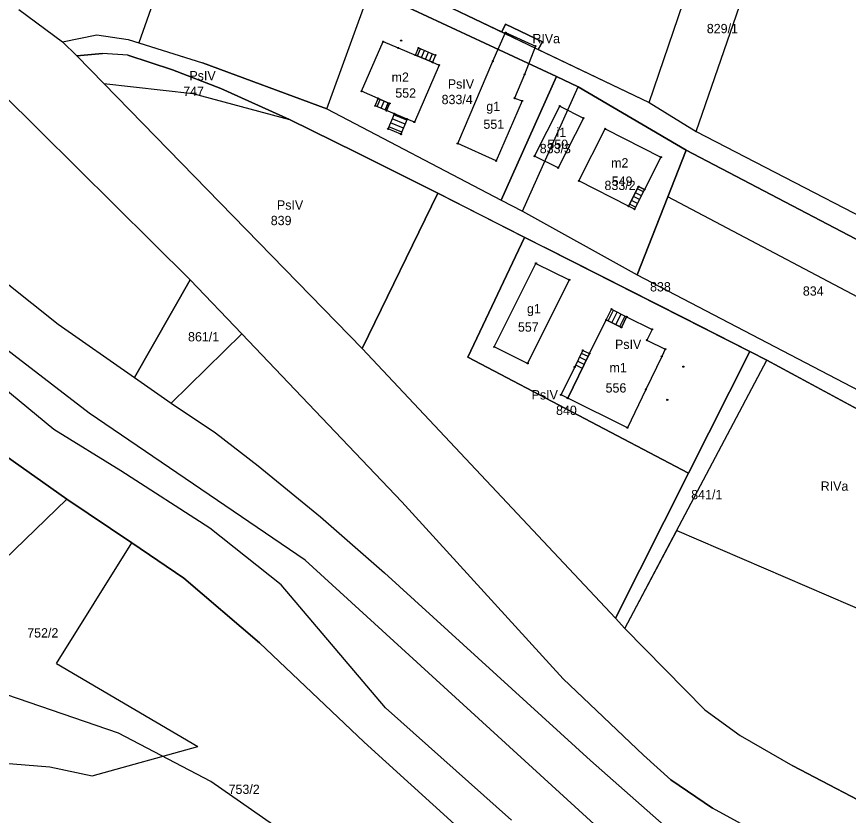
# Model space of a CAD drawing. Extents: x 7498273 to 7499989, y 5499795 to 5500810.
# Drawn here: x 7499073.7 to 7499207.8, y 5500392.1 to 5500521 of the extents above; entities that cross this region are included whole.
import ezdxf

# ---------------------------------------------------------------- set-up
doc = ezdxf.new("R2010")
doc.units = 0
for name, color, linetype in [('209-oznaczenie konturu klasyfikacyjnego', 7, 'Continuous'), ('211-numer działki ewidencyjnej', 7, 'Continuous'), ('217-kontur klasyfikacyjny', 7, 'Continuous'), ('218-kontur użytku gruntowego', 7, 'Continuous'), ('219-działka ewidencyjna', 7, 'Continuous'), ('312-budynek ewidencyjny', 7, 'Continuous'), ('312-oznaczenie budynku ewidencyjnego', 7, 'Continuous'), ('312-oznaczenie budynku ewidencyjnego-Atr117', 7, 'Continuous'), ('352-schody', 7, 'Continuous'), ('Punkt budynku', 7, 'Continuous')]:
    doc.layers.add(name, color=color, linetype=linetype)

# ---------------------------------------------------------------- blocks, each defined once
blk = doc.blocks.new('PUNKTBUD')
blk.add_circle((0, 0), 0.09)

msp = doc.modelspace()

# ---------------------------------------------------------------- linework, layer by layer
at = {"layer": '217-kontur klasyfikacyjny'}
for points in [[(7499101.11, 5500538.76), (7499093.36, 5500516.77)], [(7499131.62, 5500528.27), (7499151.94, 5500518.51)], [(7499123.69, 5500506.08), (7499130.71, 5500525.33)], [(7499160.73, 5500511.31), (7499130.71, 5500525.33)], [(7499151.94, 5500518.51), (7499152.51, 5500519.76)], [(7499152.51, 5500519.76), (7499158.46, 5500516.91)], [(7499151.94, 5500518.51), (7499157.81, 5500515.69)], [(7499093.36, 5500516.77), (7499103.62, 5500513.55)], [(7499158.46, 5500516.91), (7499157.81, 5500515.69)], [(7499087.53, 5500515.03), (7499083.37, 5500514.64)], [(7499083.37, 5500514.64), (7499087.71, 5500510.21)], [(7499091.59, 5500514.76), (7499087.53, 5500515.03)], [(7499098.81, 5500512.41), (7499091.59, 5500514.76)], [(7499157.81, 5500515.69), (7499175.67, 5500507.11)], [(7499103.62, 5500513.55), (7499123.69, 5500506.08)], [(7499106.58, 5500509.41), (7499098.81, 5500512.41)], [(7499151.82, 5500491.39), (7499160.73, 5500511.31)], [(7499160.73, 5500511.31), (7499164.26, 5500509.66)], [(7499087.71, 5500510.21), (7499102.1, 5500508.58)], [(7499087.71, 5500510.21), (7499129.4, 5500467.46)], [(7499117.68, 5500504.37), (7499106.58, 5500509.41)], [(7499164.26, 5500509.66), (7499181.67, 5500499.42)], [(7499101.66, 5500478.53), (7499071.27, 5500508.65)], [(7499102.1, 5500508.58), (7499117.68, 5500504.37)], [(7499175.67, 5500507.11), (7499183.28, 5500502.46)], [(7499123.69, 5500506.08), (7499151.82, 5500491.39)], [(7499128.46, 5500499.07), (7499117.68, 5500504.37)], [(7499183.28, 5500502.46), (7499226.11, 5500480.31)], [(7499141.59, 5500492.5), (7499128.46, 5500499.07)], [(7499181.67, 5500499.42), (7499178.7, 5500491.9)], [(7499227.23, 5500475.57), (7499181.67, 5500499.42)], [(7499129.4, 5500467.46), (7499141.59, 5500492.5)], [(7499155.6, 5500485.37), (7499141.59, 5500492.5)], [(7499178.7, 5500491.9), (7499173.73, 5500479.35)], [(7499296.61, 5500429.63), (7499178.7, 5500491.9)], [(7499055.34, 5500491.27), (7499080.34, 5500471.35)], [(7499146.42, 5500466.04), (7499155.6, 5500485.37)], [(7499158.26, 5500484.02), (7499155.6, 5500485.37)], [(7499159.07, 5500483.61), (7499158.26, 5500484.02)], [(7499181.06, 5500472.48), (7499159.07, 5500483.61)], [(7499092.66, 5500462.75), (7499101.66, 5500478.53)], [(7499109.96, 5500469.81), (7499101.66, 5500478.53)], [(7499173.73, 5500479.35), (7499219.39, 5500455.52)], [(7499191.93, 5500466.97), (7499181.06, 5500472.48)], [(7499080.34, 5500471.35), (7499092.66, 5500462.75)], [(7499135.77, 5500442.73), (7499109.96, 5500469.81)], [(7499129.4, 5500467.46), (7499170.26, 5500423.96)], [(7499182.05, 5500447.36), (7499191.93, 5500466.97)], [(7499194.67, 5500465.58), (7499191.93, 5500466.97)], [(7499182.05, 5500447.36), (7499146.42, 5500466.04)], [(7499234.45, 5500444.08), (7499194.67, 5500465.58)], [(7499092.66, 5500462.75), (7499098.6, 5500458.65)], [(7499098.6, 5500458.65), (7499105.72, 5500453.82)], [(7499105.72, 5500453.82), (7499112.62, 5500448.53)], [(7499081.74, 5500443.12), (7499071.81, 5500450.17)], [(7499112.62, 5500448.53), (7499122.67, 5500440.29)], [(7499170.26, 5500423.96), (7499182.05, 5500447.36)], [(7499092.26, 5500436.09), (7499081.74, 5500443.12)], [(7499161.8, 5500414.19), (7499135.77, 5500442.73)], [(7499122.67, 5500440.29), (7499132.99, 5500431.26)], [(7499171.77, 5500422.29), (7499180.14, 5500438.11)], [(7499180.14, 5500438.11), (7499222.1, 5500420.02)], [(7499100.61, 5500430.41), (7499092.26, 5500436.09)], [(7499112.82, 5500419.97), (7499100.61, 5500430.41)], [(7499132.99, 5500431.26), (7499166.22, 5500400.98)], [(7499170.26, 5500423.96), (7499171.77, 5500422.29)], [(7499171.77, 5500422.29), (7499184.68, 5500409.19)], [(7499129.71, 5500403.95), (7499112.82, 5500419.97)], [(7499090.07, 5500405.4), (7499064.84, 5500414.07)], [(7499174.8, 5500401.83), (7499161.8, 5500414.19)], [(7499184.68, 5500409.19), (7499190.39, 5500405)], [(7499104.96, 5500397.6), (7499090.07, 5500405.4)], [(7499190.39, 5500405), (7499198.84, 5500400.12)], [(7499155.37, 5500380.67), (7499129.71, 5500403.95)], [(7499166.22, 5500400.98), (7499189.5, 5500380.47)], [(7499179.19, 5500397.85), (7499174.8, 5500401.83)], [(7499198.84, 5500400.12), (7499214.07, 5500392.18)], [(7499128.22, 5500381.42), (7499104.96, 5500397.6)], [(7499185.89, 5500393.28), (7499179.19, 5500397.85)], [(7499197.4, 5500387.02), (7499185.89, 5500393.28)]]:
    msp.add_lwpolyline(points, dxfattribs=at)
at = {"layer": '218-kontur użytku gruntowego'}
for points in [[(7499101.11, 5500538.76), (7499093.36, 5500516.77)], [(7499131.62, 5500528.27), (7499151.94, 5500518.51)], [(7499123.69, 5500506.08), (7499130.71, 5500525.33)], [(7499160.73, 5500511.31), (7499130.71, 5500525.33)], [(7499073.99, 5500522.1), (7499081.08, 5500516.92)], [(7499152.51, 5500519.76), (7499151.94, 5500518.51)], [(7499158.46, 5500516.91), (7499152.51, 5500519.76)], [(7499081.08, 5500516.92), (7499086.58, 5500518.05)], [(7499086.58, 5500518.05), (7499091.64, 5500517.31)], [(7499091.64, 5500517.31), (7499093.36, 5500516.77)], [(7499151.94, 5500518.51), (7499157.81, 5500515.69)], [(7499093.36, 5500516.77), (7499103.62, 5500513.55)], [(7499157.81, 5500515.69), (7499158.46, 5500516.91)], [(7499087.53, 5500515.03), (7499083.37, 5500514.64)], [(7499083.37, 5500514.64), (7499087.71, 5500510.21)], [(7499091.59, 5500514.76), (7499087.53, 5500515.03)], [(7499098.81, 5500512.41), (7499091.59, 5500514.76)], [(7499157.81, 5500515.69), (7499175.67, 5500507.11)], [(7499103.62, 5500513.55), (7499123.69, 5500506.08)], [(7499106.58, 5500509.41), (7499098.81, 5500512.41)], [(7499160.73, 5500511.31), (7499151.82, 5500491.39)], [(7499164.26, 5500509.66), (7499160.73, 5500511.31)], [(7499087.71, 5500510.21), (7499102.1, 5500508.58)], [(7499087.71, 5500510.21), (7499129.4, 5500467.46)], [(7499117.68, 5500504.37), (7499106.58, 5500509.41)], [(7499181.67, 5500499.42), (7499164.26, 5500509.66)], [(7499101.66, 5500478.53), (7499071.27, 5500508.65)], [(7499102.1, 5500508.58), (7499117.68, 5500504.37)], [(7499175.67, 5500507.11), (7499183.28, 5500502.46)], [(7499123.69, 5500506.08), (7499151.82, 5500491.39)], [(7499128.46, 5500499.07), (7499117.68, 5500504.37)], [(7499183.28, 5500502.46), (7499226.11, 5500480.31)], [(7499141.59, 5500492.5), (7499128.46, 5500499.07)], [(7499181.67, 5500499.42), (7499178.7, 5500491.9)], [(7499227.23, 5500475.57), (7499181.67, 5500499.42)], [(7499085.38, 5500457), (7499035.99, 5500494.95)], [(7499141.59, 5500492.5), (7499129.4, 5500467.46)], [(7499155.6, 5500485.37), (7499141.59, 5500492.5)], [(7499178.7, 5500491.9), (7499173.73, 5500479.35)], [(7499296.61, 5500429.63), (7499178.7, 5500491.9)], [(7499055.34, 5500491.27), (7499080.34, 5500471.35)], [(7499151.82, 5500491.39), (7499155.28, 5500489.58)], [(7499155.28, 5500489.58), (7499173.73, 5500479.35)], [(7499155.6, 5500485.37), (7499146.42, 5500466.04)], [(7499158.26, 5500484.02), (7499155.6, 5500485.37)], [(7499159.07, 5500483.61), (7499158.26, 5500484.02)], [(7499181.06, 5500472.48), (7499159.07, 5500483.61)], [(7499079.66, 5500454.39), (7499047.93, 5500480.59)], [(7499101.66, 5500478.53), (7499092.66, 5500462.75)], [(7499109.96, 5500469.81), (7499101.66, 5500478.53)], [(7499173.73, 5500479.35), (7499219.39, 5500455.52)], [(7499191.93, 5500466.97), (7499181.06, 5500472.48)], [(7499080.34, 5500471.35), (7499092.66, 5500462.75)], [(7499135.77, 5500442.73), (7499109.96, 5500469.81)], [(7499129.4, 5500467.46), (7499170.26, 5500423.96)], [(7499191.93, 5500466.97), (7499182.05, 5500447.36)], [(7499194.67, 5500465.58), (7499191.93, 5500466.97)], [(7499146.42, 5500466.04), (7499182.05, 5500447.36)], [(7499234.45, 5500444.08), (7499194.67, 5500465.58)], [(7499092.66, 5500462.75), (7499098.6, 5500458.65)], [(7499098.6, 5500458.65), (7499105.72, 5500453.82)], [(7499120.19, 5500433.29), (7499085.38, 5500457)], [(7499090.49, 5500447.7), (7499079.66, 5500454.39)], [(7499105.72, 5500453.82), (7499112.62, 5500448.53)], [(7499071.81, 5500450.17), (7499081.74, 5500443.12)], [(7499104.8, 5500438.49), (7499090.49, 5500447.7)], [(7499112.62, 5500448.53), (7499122.67, 5500440.29)], [(7499182.05, 5500447.36), (7499170.26, 5500423.96)], [(7499081.74, 5500443.12), (7499092.26, 5500436.09)], [(7499161.8, 5500414.19), (7499135.77, 5500442.73)], [(7499122.67, 5500440.29), (7499132.99, 5500431.26)], [(7499116.34, 5500429.34), (7499104.8, 5500438.49)], [(7499171.77, 5500422.29), (7499180.14, 5500438.11)], [(7499180.14, 5500438.11), (7499222.1, 5500420.02)], [(7499092.26, 5500436.09), (7499100.61, 5500430.41)], [(7499171.15, 5500386.77), (7499120.19, 5500433.29)], [(7499100.61, 5500430.41), (7499112.82, 5500419.97)], [(7499132.99, 5500431.26), (7499166.22, 5500400.98)], [(7499133.15, 5500409.51), (7499116.34, 5500429.34)], [(7499170.26, 5500423.96), (7499171.77, 5500422.29)], [(7499171.77, 5500422.29), (7499184.68, 5500409.19)], [(7499112.82, 5500419.97), (7499129.71, 5500403.95)], [(7499090.07, 5500405.4), (7499064.84, 5500414.07)], [(7499174.8, 5500401.83), (7499161.8, 5500414.19)], [(7499153.5, 5500391.37), (7499133.15, 5500409.51)], [(7499184.68, 5500409.19), (7499190.39, 5500405)], [(7499104.96, 5500397.6), (7499090.07, 5500405.4)], [(7499190.39, 5500405), (7499198.84, 5500400.12)], [(7499129.71, 5500403.95), (7499155.37, 5500380.67)], [(7499166.22, 5500400.98), (7499189.5, 5500380.47)], [(7499179.19, 5500397.85), (7499174.8, 5500401.83)], [(7499198.84, 5500400.12), (7499214.07, 5500392.18)], [(7499128.22, 5500381.42), (7499104.96, 5500397.6)], [(7499185.89, 5500393.28), (7499179.19, 5500397.85)], [(7499197.4, 5500387.02), (7499185.89, 5500393.28)]]:
    msp.add_lwpolyline(points, dxfattribs=at)
at = {"layer": '219-działka ewidencyjna'}
for points in [[(7499175.67, 5500507.11), (7499185.88, 5500537.14)], [(7499183.28, 5500502.46), (7499194.31, 5500534.37)], [(7499131.62, 5500528.27), (7499175.67, 5500507.11)], [(7499123.69, 5500506.08), (7499130.71, 5500525.33)], [(7499130.71, 5500525.33), (7499160.73, 5500511.31)], [(7499073.99, 5500522.1), (7499081.08, 5500516.92)], [(7499081.08, 5500516.92), (7499086.58, 5500518.05)], [(7499086.58, 5500518.05), (7499091.64, 5500517.31)], [(7499091.64, 5500517.31), (7499103.62, 5500513.55)], [(7499081.08, 5500516.92), (7499083.37, 5500514.64)], [(7499083.37, 5500514.64), (7499087.53, 5500515.03)], [(7499083.37, 5500514.64), (7499087.71, 5500510.21)], [(7499091.59, 5500514.76), (7499087.53, 5500515.03)], [(7499091.59, 5500514.76), (7499098.81, 5500512.41)], [(7499123.69, 5500506.08), (7499103.62, 5500513.55)], [(7499098.81, 5500512.41), (7499106.58, 5500509.41)], [(7499151.82, 5500491.39), (7499160.73, 5500511.31)], [(7499160.73, 5500511.31), (7499164.26, 5500509.66)], [(7499087.71, 5500510.21), (7499129.4, 5500467.46)], [(7499087.71, 5500510.21), (7499102.1, 5500508.58)], [(7499106.58, 5500509.41), (7499117.68, 5500504.37)], [(7499155.28, 5500489.58), (7499164.26, 5500509.66)], [(7499164.26, 5500509.66), (7499181.67, 5500499.42)], [(7499071.27, 5500508.65), (7499101.66, 5500478.53)], [(7499102.1, 5500508.58), (7499117.68, 5500504.37)], [(7499175.67, 5500507.11), (7499183.28, 5500502.46)], [(7499123.69, 5500506.08), (7499151.82, 5500491.39)], [(7499117.68, 5500504.37), (7499128.46, 5500499.07)], [(7499183.28, 5500502.46), (7499226.11, 5500480.31)], [(7499128.46, 5500499.07), (7499141.59, 5500492.5)], [(7499173.73, 5500479.35), (7499181.67, 5500499.42)], [(7499181.67, 5500499.42), (7499227.23, 5500475.57)], [(7499129.4, 5500467.46), (7499141.59, 5500492.5)], [(7499141.59, 5500492.5), (7499159.07, 5500483.61)], [(7499055.34, 5500491.27), (7499080.34, 5500471.35)], [(7499151.82, 5500491.39), (7499155.28, 5500489.58)], [(7499155.28, 5500489.58), (7499173.73, 5500479.35)], [(7499159.07, 5500483.61), (7499191.93, 5500466.97)], [(7499092.66, 5500462.75), (7499101.66, 5500478.53)], [(7499101.66, 5500478.53), (7499109.96, 5500469.81)], [(7499173.73, 5500479.35), (7499219.39, 5500455.52)], [(7499080.34, 5500471.35), (7499092.66, 5500462.75)], [(7499098.6, 5500458.65), (7499109.96, 5500469.81)], [(7499109.96, 5500469.81), (7499135.77, 5500442.73)], [(7499129.4, 5500467.46), (7499170.26, 5500423.96)], [(7499170.26, 5500423.96), (7499191.93, 5500466.97)], [(7499191.93, 5500466.97), (7499194.67, 5500465.58)], [(7499171.77, 5500422.29), (7499194.67, 5500465.58)], [(7499194.67, 5500465.58), (7499266.92, 5500426.53)], [(7499092.66, 5500462.75), (7499098.6, 5500458.65)], [(7499098.6, 5500458.65), (7499105.72, 5500453.82)], [(7499105.72, 5500453.82), (7499112.62, 5500448.53)], [(7499071.81, 5500450.17), (7499081.74, 5500443.12)], [(7499112.62, 5500448.53), (7499122.67, 5500440.29)], [(7499058.06, 5500420.25), (7499081.74, 5500443.12)], [(7499081.74, 5500443.12), (7499092.26, 5500436.09)], [(7499135.77, 5500442.73), (7499161.8, 5500414.19)], [(7499122.67, 5500440.29), (7499132.99, 5500431.26)], [(7499080.08, 5500416.64), (7499092.26, 5500436.09)], [(7499092.26, 5500436.09), (7499100.61, 5500430.41)], [(7499100.61, 5500430.41), (7499112.82, 5500419.97)], [(7499166.22, 5500400.98), (7499132.99, 5500431.26)], [(7499170.26, 5500423.96), (7499171.77, 5500422.29)], [(7499171.77, 5500422.29), (7499184.68, 5500409.19)], [(7499112.82, 5500419.97), (7499129.71, 5500403.95)], [(7499080.08, 5500416.64), (7499102.88, 5500403.24)], [(7499161.8, 5500414.19), (7499174.8, 5500401.83)], [(7499184.68, 5500409.19), (7499190.39, 5500405)], [(7499190.39, 5500405), (7499198.84, 5500400.12)], [(7499129.71, 5500403.95), (7499155.37, 5500380.67)], [(7499085.87, 5500398.54), (7499102.88, 5500403.24)], [(7499064.37, 5500401.18), (7499079.03, 5500399.99)], [(7499166.22, 5500400.98), (7499189.5, 5500380.47)], [(7499174.8, 5500401.83), (7499179.19, 5500397.85)], [(7499079.03, 5500399.99), (7499085.87, 5500398.54)], [(7499214.07, 5500392.18), (7499198.84, 5500400.12)], [(7499179.19, 5500397.85), (7499185.89, 5500393.28)], [(7499197.4, 5500387.02), (7499185.89, 5500393.28)]]:
    msp.add_lwpolyline(points, dxfattribs=at)
at = {"layer": '312-budynek ewidencyjny'}
for points in [[(7499150.46, 5500513.8), (7499152.54, 5500518.39)], [(7499152.54, 5500518.39), (7499157.35, 5500516.21)], [(7499129.3, 5500508.94), (7499132.77, 5500516.95)], [(7499132.77, 5500516.95), (7499135.2, 5500515.93)], [(7499157.35, 5500516.21), (7499155.57, 5500511.63)], [(7499135.2, 5500515.93), (7499137.98, 5500514.77)], [(7499137.98, 5500514.77), (7499140.75, 5500513.61)], [(7499140.75, 5500513.61), (7499141.82, 5500513.16)], [(7499144.8, 5500500.51), (7499150.46, 5500513.8)], [(7499141.82, 5500513.16), (7499137.81, 5500503.97)], [(7499155.57, 5500511.63), (7499153.96, 5500507.83)], [(7499131.99, 5500507.77), (7499129.3, 5500508.94)], [(7499133.83, 5500506.98), (7499131.99, 5500507.77)], [(7499133.33, 5500505.81), (7499133.83, 5500506.98)], [(7499155.21, 5500507.37), (7499151.01, 5500497.71)], [(7499153.96, 5500507.83), (7499155.21, 5500507.37)], [(7499157.21, 5500498.47), (7499161.29, 5500506.56)], [(7499161.29, 5500506.56), (7499165.11, 5500504.6)], [(7499134.59, 5500505.29), (7499133.33, 5500505.81)], [(7499136.65, 5500504.45), (7499134.59, 5500505.29)], [(7499137.81, 5500503.97), (7499136.65, 5500504.45)], [(7499165.11, 5500504.6), (7499161, 5500496.58)], [(7499164.35, 5500494.48), (7499168.6, 5500502.88)], [(7499168.6, 5500502.88), (7499177.59, 5500498.3)], [(7499151.01, 5500497.71), (7499144.8, 5500500.51)], [(7499161, 5500496.58), (7499157.21, 5500498.47)], [(7499177.59, 5500498.3), (7499174.93, 5500493.07)], [(7499172.37, 5500490.39), (7499164.35, 5500494.48)], [(7499173.98, 5500493.56), (7499172.37, 5500490.39)], [(7499174.93, 5500493.07), (7499173.98, 5500493.56)], [(7499150.69, 5500467.7), (7499157.43, 5500481.18)], [(7499157.43, 5500481.18), (7499162.81, 5500478.52)], [(7499162.81, 5500478.52), (7499156.09, 5500465.05)], [(7499166.08, 5500466.62), (7499168.76, 5500472.07)], [(7499168.76, 5500472.07), (7499171.2, 5500470.86)], [(7499171.2, 5500470.86), (7499172.05, 5500472.57)], [(7499172.05, 5500472.57), (7499176.16, 5500470.53)], [(7499176.16, 5500470.53), (7499175.31, 5500468.79)], [(7499156.09, 5500465.05), (7499150.69, 5500467.7)], [(7499175.31, 5500468.79), (7499178.29, 5500467.35)], [(7499162.55, 5500459.44), (7499166.08, 5500466.62)], [(7499178.29, 5500467.35), (7499177.72, 5500466.18)], [(7499177.72, 5500466.18), (7499175.15, 5500460.83)], [(7499175.15, 5500460.83), (7499172.18, 5500454.67)], [(7499172.18, 5500454.67), (7499162.55, 5500459.44)]]:
    msp.add_lwpolyline(points, dxfattribs=at)
at = {"layer": '352-schody'}
for points in [[(7499138.47, 5500515.93), (7499141.24, 5500514.77), (7499140.75, 5500513.61), (7499137.98, 5500514.77)], [(7499138.47, 5500515.93), (7499141.24, 5500514.77), (7499140.75, 5500513.61), (7499137.98, 5500514.77)], [(7499131.99, 5500507.77), (7499133.83, 5500506.98), (7499133.33, 5500505.81), (7499131.49, 5500506.6)], [(7499131.99, 5500507.77), (7499133.83, 5500506.98), (7499133.33, 5500505.81), (7499131.49, 5500506.6)], [(7499133.59, 5500502.86), (7499134.59, 5500505.29), (7499136.65, 5500504.45), (7499135.65, 5500502.02)], [(7499133.59, 5500502.86), (7499134.59, 5500505.29), (7499136.65, 5500504.45), (7499135.65, 5500502.02)], [(7499172.37, 5500490.39), (7499173.98, 5500493.56), (7499174.93, 5500493.07), (7499173.32, 5500489.91)], [(7499172.37, 5500490.39), (7499173.98, 5500493.56), (7499174.93, 5500493.07), (7499173.32, 5500489.91)], [(7499168.76, 5500472.07), (7499169.61, 5500473.79), (7499172.05, 5500472.57), (7499171.2, 5500470.86)], [(7499168.76, 5500472.07), (7499169.61, 5500473.79), (7499172.05, 5500472.57), (7499171.2, 5500470.86)], [(7499161.47, 5500459.97), (7499163.68, 5500464.46), (7499165, 5500467.15), (7499166.08, 5500466.62), (7499162.55, 5500459.44)], [(7499161.47, 5500459.97), (7499163.68, 5500464.46), (7499165, 5500467.15), (7499166.08, 5500466.62), (7499162.55, 5500459.44)]]:
    msp.add_lwpolyline(points, close=True, dxfattribs=at)
for points in [[(7499138.306, 5500514.633), (7499138.793, 5500515.795)], [(7499138.952, 5500514.363), (7499139.439, 5500515.524)], [(7499139.598, 5500514.093), (7499140.084, 5500515.254)], [(7499140.243, 5500513.822), (7499140.73, 5500514.984)], [(7499131.81, 5500506.463), (7499132.312, 5500507.632)], [(7499132.453, 5500506.187), (7499132.955, 5500507.356)], [(7499133.096, 5500505.91), (7499133.598, 5500507.08)], [(7499136.313, 5500503.632), (7499134.256, 5500504.478)], [(7499136.58, 5500504.279), (7499134.522, 5500505.126)], [(7499135.78, 5500502.337), (7499133.723, 5500503.184)], [(7499136.047, 5500502.984), (7499133.99, 5500503.831)], [(7499174.749, 5500492.715), (7499173.796, 5500493.199)], [(7499174.113, 5500491.467), (7499173.162, 5500491.95)], [(7499174.431, 5500492.091), (7499173.479, 5500492.574)], [(7499173.478, 5500490.22), (7499172.528, 5500490.702)], [(7499173.796, 5500490.844), (7499172.845, 5500491.326)], [(7499169.066, 5500471.918), (7499169.923, 5500473.633)], [(7499169.693, 5500471.607), (7499170.549, 5500473.32)], [(7499170.32, 5500471.296), (7499171.175, 5500473.007)], [(7499170.947, 5500470.985), (7499171.801, 5500472.694)], [(7499165.839, 5500466.13), (7499164.759, 5500466.659)], [(7499165.221, 5500464.873), (7499164.143, 5500465.403)], [(7499165.53, 5500465.501), (7499164.451, 5500466.031)], [(7499164.912, 5500464.245), (7499163.834, 5500464.774)]]:
    msp.add_lwpolyline(points, dxfattribs=at)

# ---------------------------------------------------------------- block references
at = {"layer": 'Punkt budynku'}
for p in [(7499152.54, 5500518.39), (7499132.77, 5500516.95), (7499135.2, 5500515.93), (7499135.69, 5500517.1), (7499138.47, 5500515.93), (7499157.35, 5500516.21), (7499137.98, 5500514.77), (7499141.24, 5500514.77), (7499140.75, 5500513.61), (7499150.46, 5500513.8), (7499141.82, 5500513.16), (7499155.57, 5500511.63), (7499129.3, 5500508.94), (7499153.96, 5500507.83), (7499131.49, 5500506.6), (7499131.99, 5500507.77), (7499133.83, 5500506.98), (7499155.21, 5500507.37), (7499161.29, 5500506.56), (7499133.33, 5500505.81), (7499134.59, 5500505.29), (7499136.65, 5500504.45), (7499137.81, 5500503.97), (7499165.11, 5500504.6), (7499133.59, 5500502.86), (7499168.6, 5500502.88), (7499135.65, 5500502.02), (7499144.8, 5500500.51), (7499157.21, 5500498.47), (7499151.01, 5500497.71), (7499177.59, 5500498.3), (7499161, 5500496.58), (7499164.35, 5500494.48), (7499173.98, 5500493.56), (7499174.93, 5500493.07), (7499172.37, 5500490.39), (7499173.32, 5500489.91), (7499157.43, 5500481.18), (7499162.81, 5500478.52), (7499169.61, 5500473.79), (7499168.76, 5500472.07), (7499172.05, 5500472.57), (7499171.2, 5500470.86), (7499176.16, 5500470.53), (7499150.69, 5500467.7), (7499175.31, 5500468.79), (7499165, 5500467.15), (7499166.08, 5500466.62), (7499178.29, 5500467.35), (7499156.09, 5500465.05), (7499177.72, 5500466.18), (7499163.68, 5500464.46), (7499181.19, 5500464.51), (7499161.47, 5500459.97), (7499175.15, 5500460.83), (7499162.55, 5500459.44), (7499178.61, 5500459.16), (7499172.18, 5500454.67)]:
    msp.add_blockref('PUNKTBUD', p, dxfattribs=at)

# ---------------------------------------------------------------- texts
at = {"layer": '209-oznaczenie konturu klasyfikacyjnego'}
for s, p in [('RIVa', (7499156.85, 5500516.69)), ('PsIV', (7499101.53, 5500510.7)), ('PsIV', (7499143.21, 5500509.36)), ('PsIV', (7499115.65, 5500489.84)), ('PsIV', (7499170.18, 5500467.37)), ('PsIV', (7499156.73, 5500459.23)), ('RIVa', (7499203.36, 5500444.5))]:
    msp.add_text(s, height=1.5, dxfattribs=at).set_placement(p)
at = {"layer": '211-numer działki ewidencyjnej'}
for s, p in [('829/1', (7499184.99, 5500518.3)), ('747', (7499100.53, 5500508.2)), ('833/4', (7499142.21, 5500506.86)), ('833/3', (7499158.04, 5500498.95)), ('833/2', (7499168.48, 5500493.01)), ('839', (7499114.65, 5500487.34)), ('838', (7499175.83, 5500476.65)), ('834', (7499200.48, 5500475.97)), ('861/1', (7499101.31, 5500468.59)), ('840', (7499160.67, 5500456.73)), ('841/1', (7499182.47, 5500443.13)), ('752/2', (7499075.37, 5500420.83)), ('753/2', (7499107.85, 5500395.6))]:
    msp.add_text(s, height=1.5, dxfattribs=at).set_placement(p)
at = {"layer": '312-oznaczenie budynku ewidencyjnego'}
for s, p in [('552', (7499134.74, 5500507.9)), ('551', (7499148.95, 5500502.88)), ('550', (7499159.27, 5500499.64)), ('549', (7499169.65, 5500493.69)), ('557', (7499154.52, 5500470.16)), ('556', (7499168.66, 5500460.34))]:
    msp.add_text(s, height=1.5, dxfattribs=at).set_placement(p)
at = {"layer": '312-oznaczenie budynku ewidencyjnego-Atr117'}
for s, p in [('m2', (7499134.146, 5500510.46)), ('g1', (7499149.419, 5500505.76)), ('i1', (7499160.742, 5500501.57)), ('m2', (7499169.556, 5500496.64)), ('g1', (7499155.979, 5500473.12)), ('m1', (7499169.295, 5500463.62))]:
    msp.add_text(s, height=1.5, dxfattribs=at).set_placement(p)

doc.saveas('drawing.dxf')
